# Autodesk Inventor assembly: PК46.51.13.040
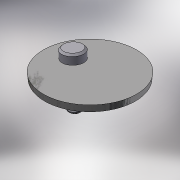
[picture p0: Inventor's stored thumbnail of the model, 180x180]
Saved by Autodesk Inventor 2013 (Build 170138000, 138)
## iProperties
Created: 2005-04
Part Number: PК46.51.13.040
Document SubType Name: Assembly
Designer: =<Author>
Manufacturer: Standard
Standards Organization: Custom
Description: strip
Mass: 59.2351 g
Surface Area: 54.3482 cm^2
Volume: 7.64323 cm^3
Density: 7.75 g/cm^3
Author: PVitaliy
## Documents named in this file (3)
- Y:\Dropbox\Launch 2013\Eco Material Advisor\Assy, Door\_Data\Assy, Cab\PK46.51.13.040.iam
- Y:\Dropbox\Launch 2013\Eco Material Advisor\Assy, Door\_Data\Assy, Cab\support for a new pen.ipt
- Y:\Dropbox\Launch 2013\Eco Material Advisor\Assy, Door\_Data\Assy, Cab\PK46.51.13.007.ipt
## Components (2 placed, 2 different names)
1. support for a new pen:1 — Insert:1
2. PK46.51.13.007:1 — Insert:1
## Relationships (1: Insert 1)
- Insert:1: support for a new pen:1 ↔ PK46.51.13.007:1
